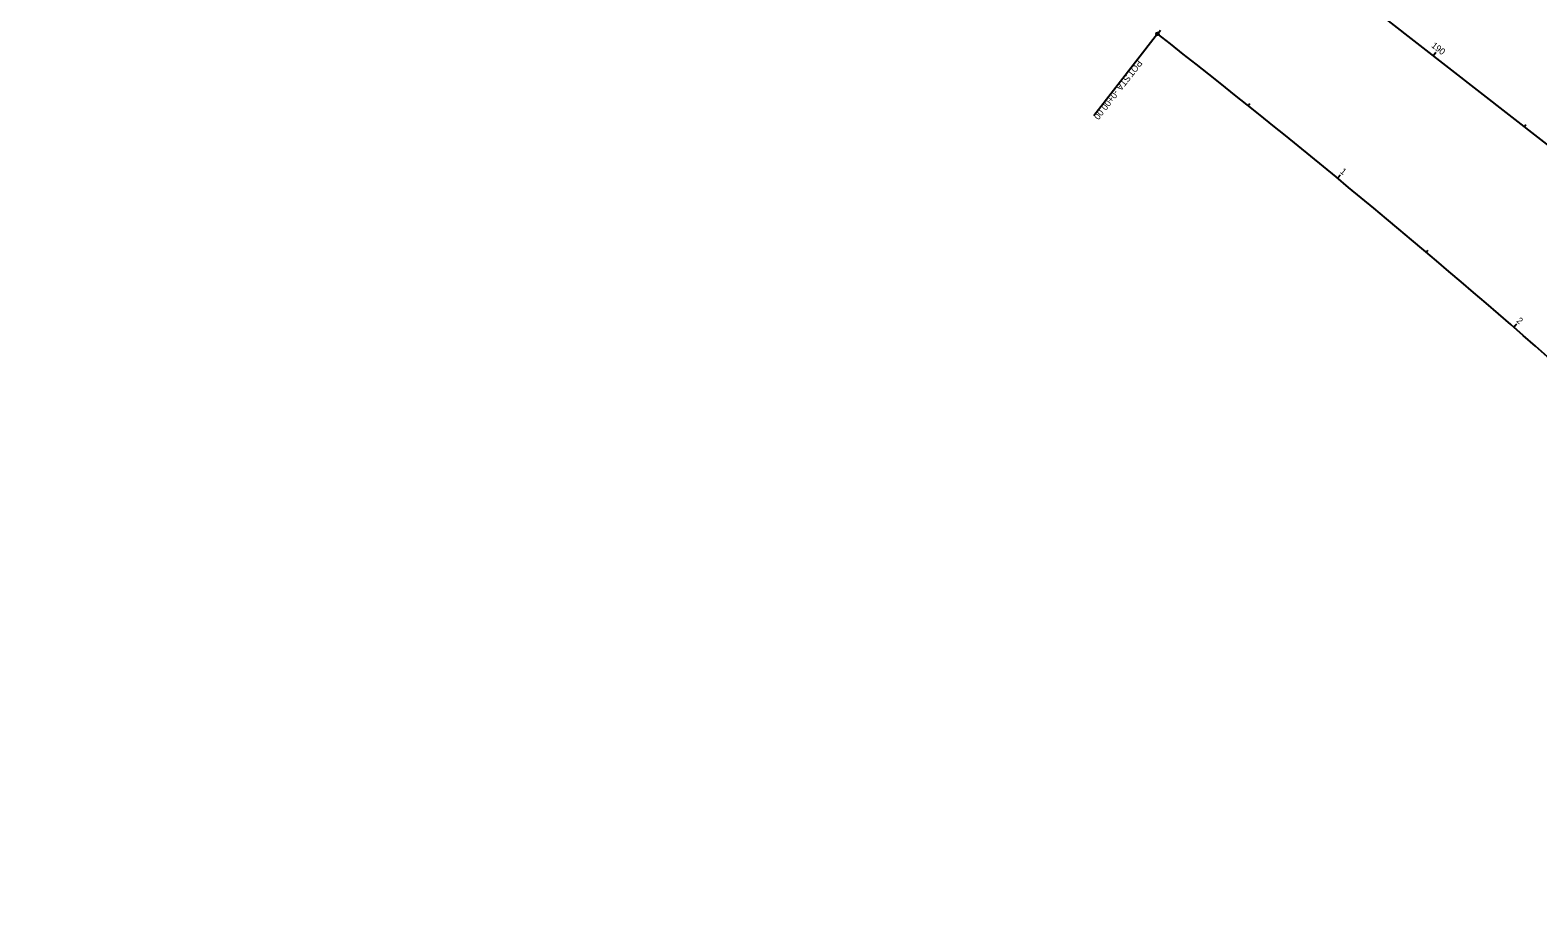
# Model space of a CAD drawing. Extents: x 1323137 to 1326838, y 458936 to 461644.
# Drawn here: x 1323791 to 1324445, y 460248 to 460634 of the extents above; entities that cross this region are included whole.
import ezdxf

# ---------------------------------------------------------------- set-up
doc = ezdxf.new("R2010")
doc.units = 0
for name, color, linetype in [('_CIVIL_CONSTRUCTION', 7, 'Continuous'), ('CM_Corridor_Range_Final', 7, 'Continuous'), ('Default', 7, 'Continuous'), ('MD_P_Surface_Asphalt_Concrete_Intermediate_Course', 7, 'Continuous'), ('SN_P_Signs', 7, 'Continuous'), ('SN_X_Public', 7, 'Continuous')]:
    doc.layers.add(name, color=color, linetype=linetype)

msp = doc.modelspace()

# ---------------------------------------------------------------- linework, layer by layer
at = {"layer": '_CIVIL_CONSTRUCTION'}
msp.add_line((1324279.75, 460632.56), (1324252.07, 460597.08), dxfattribs=at)
msp.add_circle((1324279.75, 460632.56), 0.6, dxfattribs=at)
at = {"layer": 'CM_Corridor_Range_Final'}
for p, q in [((1324279.75, 460632.56), (1324280.98, 460634.14)), ((1324399.19, 460623.1), (1324400.42, 460624.67)), ((1324318.97, 460601.55), (1324319.72, 460602.49)), ((1324438.61, 460592.34), (1324439.35, 460593.29)), ((1324357.78, 460570.03), (1324359.05, 460571.58)), ((1324396.18, 460538), (1324396.95, 460538.92)), ((1324434.15, 460505.48), (1324435.46, 460506.99))]:
    msp.add_line(p, q, dxfattribs=at)
at = {"layer": 'Default'}
msp.add_line((1323137.63, 461607.2), (1324879.49, 460248.43), dxfattribs=at)
at = {"layer": 'MD_P_Surface_Asphalt_Concrete_Intermediate_Course'}
msp.add_line((1324279.75, 460632.56), (1324252.07, 460597.08), dxfattribs=at)
msp.add_circle((1324279.75, 460632.56), 0.6, dxfattribs=at)
at = {"layer": 'SN_P_Signs'}
msp.add_line((1323137.63, 461607.2), (1324879.49, 460248.43), dxfattribs=at)
msp.add_arc((1321930.37, 457620.81), 3819.72, 45.2472, 52.04331, dxfattribs=at)
at = {"layer": 'SN_X_Public'}
for p, q in [((1324279.75, 460632.56), (1324280.98, 460634.14)), ((1324399.19, 460623.1), (1324400.42, 460624.67)), ((1324357.78, 460570.03), (1324358.54, 460570.96)), ((1324434.15, 460505.48), (1324434.94, 460506.38))]:
    msp.add_line(p, q, dxfattribs=at)

# ---------------------------------------------------------------- texts
at = {"layer": '_CIVIL_CONSTRUCTION'}
for s, p in [('POT', (1324271.19, 460621.53)), (' STA. ', (1324266.81, 460615.91)), ('-0+00.00', (1324261.07, 460608.56))]:
    msp.add_text(s, height=2.8, rotation=232.04331, dxfattribs=at).set_placement(p)
at = {"layer": 'CM_Corridor_Range_Final'}
for s, rotation, p in [('190', 322.04331, (1324398.15, 460627.08)), ('1', 320.54331, (1324358.61, 460572.59)), ('2', 319.04331, (1324435.05, 460508.01))]:
    msp.add_text(s, height=2.8, rotation=rotation, dxfattribs=at).set_placement(p)
at = {"layer": 'MD_P_Surface_Asphalt_Concrete_Intermediate_Course'}
for s, p in [('POT', (1324271.19, 460621.53)), (' STA. ', (1324266.81, 460615.91)), ('-0+00.00', (1324261.07, 460608.56))]:
    msp.add_text(s, height=2.8, rotation=232.04331, dxfattribs=at).set_placement(p)
at = {"layer": 'SN_X_Public'}
msp.add_text('190', height=2.8, rotation=322.04331, dxfattribs=at).set_placement((1324398.15, 460627.08))

doc.saveas('drawing.dxf')
